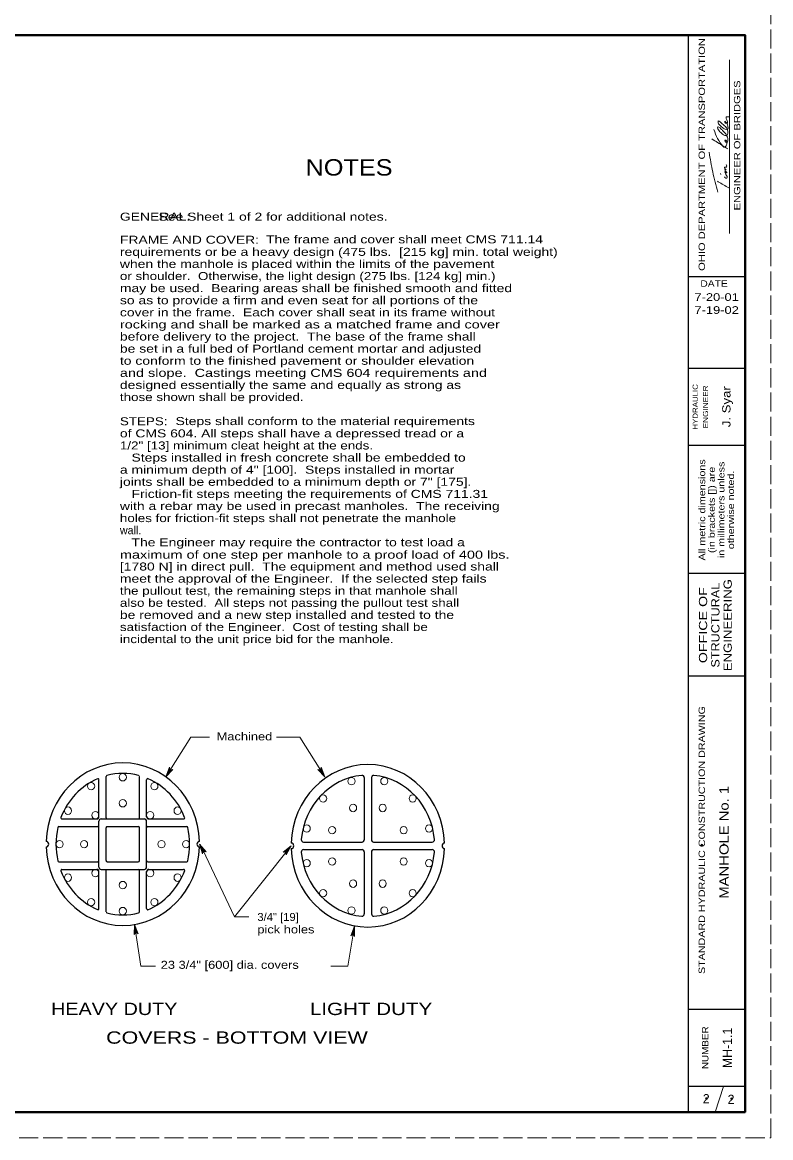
# Model space of a CAD drawing. Extents: x 1083.1 to 1117.1, y 697.4 to 741.4.
# Drawn here: x 1102.54 to 1117.13, y 697.35 to 719.1 of the extents above; entities that cross this region are included whole.
import ezdxf
from ezdxf.enums import TextEntityAlignment as Align

# ---------------------------------------------------------------- set-up
doc = ezdxf.new("R2010")
doc.units = 0
doc.header["$LTSCALE"] = 0.062
doc.header["$PDMODE"] = 32
doc.header["$PDSIZE"] = 0.031
doc.linetypes.add('LONG_DASHED', pattern=[7.5, 6, -1.5])
doc.layers.add('1', color=7, linetype='Continuous', lineweight=13)

msp = doc.modelspace()

# ---------------------------------------------------------------- linework, layer by layer
at = {"layer": '1', "lineweight": 25}
for p, q in [((1085.12642, 718.85408), (1116.62642, 718.85408)), ((1115.52642, 697.85408), (1115.52642, 718.85408)), ((1116.62642, 718.85408), (1116.62642, 697.85408)), ((1116.62642, 714.13825), (1115.52642, 714.13825)), ((1116.62642, 712.35408), (1115.52642, 712.35408)), ((1116.62642, 710.85408), (1115.52642, 710.85408)), ((1116.62642, 708.35408), (1115.52642, 708.35408)), ((1116.62642, 706.35408), (1115.52642, 706.35408)), ((1104.03592, 703.61325), (1104.03592, 704.33367)), ((1104.1765, 703.59125), (1104.1765, 704.39617)), ((1104.82367, 703.59125), (1104.82367, 704.39617)), ((1104.96425, 703.61325), (1104.96425, 704.33367)), ((1109.20633, 704.37508), (1109.20633, 703.164)), ((1109.34692, 704.37508), (1109.34692, 703.164)), ((1103.25483, 703.42042), (1104.01517, 703.42042)), ((1103.31392, 703.56925), (1103.99442, 703.56925)), ((1104.03592, 702.63042), (1104.03592, 703.52525)), ((1104.0775, 703.56925), (1104.92275, 703.56925)), ((1104.1765, 702.75725), (1104.1765, 703.39842)), ((1104.19725, 703.42042), (1104.80292, 703.42042)), ((1104.82367, 702.75725), (1104.82367, 703.39842)), ((1104.96425, 702.63042), (1104.96425, 703.52525)), ((1104.985, 703.42042), (1105.74533, 703.42042)), ((1105.00575, 703.56925), (1105.68633, 703.56925)), ((1108.02083, 703.12), (1109.16483, 703.12)), ((1108.02083, 702.97117), (1109.16483, 702.97117)), ((1109.3885, 703.12), (1110.53242, 703.12)), ((1109.3885, 702.97117), (1110.53242, 702.97117)), ((1109.20633, 702.92725), (1109.20633, 701.71608)), ((1109.34692, 702.92725), (1109.34692, 701.71608)), ((1103.25483, 702.73525), (1104.01517, 702.73525)), ((1103.31392, 702.58642), (1103.99442, 702.58642)), ((1104.03592, 701.822), (1104.03592, 702.54242)), ((1104.0775, 702.58642), (1104.92275, 702.58642)), ((1104.1765, 701.7595), (1104.1765, 702.56442)), ((1104.19725, 702.73525), (1104.80292, 702.73525)), ((1104.82367, 701.7595), (1104.82367, 702.56442)), ((1104.96425, 701.822), (1104.96425, 702.54242)), ((1104.985, 702.73525), (1105.74533, 702.73525)), ((1105.00575, 702.58642), (1105.68625, 702.58642)), ((1116.62642, 699.85408), (1115.52642, 699.85408)), ((1116.62642, 698.35408), (1115.52642, 698.35408))]:
    msp.add_line(p, q, dxfattribs=at)
at = {"layer": '1'}
for p, q in [((1116.32517, 714.98508), (1116.32517, 718.37517)), ((1116.15767, 716.136), (1116.1475, 716.15525)), ((1105.828, 705.16567), (1105.33583, 704.39183)), ((1106.19217, 705.16567), (1105.828, 705.16567)), ((1107.94875, 705.16567), (1107.49875, 705.16567)), ((1107.94875, 705.16567), (1108.44083, 704.39183)), ((1105.40967, 704.55383), (1105.33583, 704.39183)), ((1105.41675, 704.54225), (1105.33583, 704.39183)), ((1105.42625, 704.534), (1105.33583, 704.39183)), ((1105.44133, 704.52817), (1105.33583, 704.39183)), ((1105.45458, 704.52775), (1105.33583, 704.39183)), ((1108.3255, 704.52733), (1108.44083, 704.39183)), ((1108.339, 704.52892), (1108.44083, 704.39183)), ((1108.35042, 704.534), (1108.44083, 704.39183)), ((1108.36217, 704.54517), (1108.44083, 704.39183)), ((1108.36817, 704.557), (1108.44083, 704.39183)), ((1106.0775, 702.93008), (1105.99642, 703.07783)), ((1106.06508, 702.91975), (1105.99642, 703.07783)), ((1106.05833, 702.90833), (1105.99642, 703.07783)), ((1106.08925, 702.9345), (1105.99642, 703.07783)), ((1106.10283, 702.93517), (1105.99642, 703.07783)), ((1107.78033, 703.04558), (1106.67767, 701.66183)), ((1107.64375, 702.92767), (1107.78033, 703.04558)), ((1107.65683, 702.92542), (1107.78033, 703.04558)), ((1107.67092, 702.9175), (1107.78033, 703.04558)), ((1107.67917, 702.908), (1107.78033, 703.04558)), ((1107.68458, 702.89558), (1107.78033, 703.04558)), ((1104.73, 701.3335), (1104.7315, 701.51392)), ((1104.75558, 701.34717), (1104.7315, 701.51392)), ((1104.74033, 701.34183), (1104.7315, 701.51392)), ((1104.76817, 701.34717), (1104.7315, 701.51392)), ((1104.78108, 701.343), (1104.7315, 701.51392)), ((1104.7315, 701.51392), (1104.85175, 700.7015)), ((1109.01383, 701.47558), (1108.88433, 700.7015)), ((1108.956, 701.30467), (1109.01383, 701.47558)), ((1108.9685, 701.30933), (1109.01383, 701.47558)), ((1108.98458, 701.30958), (1109.01383, 701.47558)), ((1108.99658, 701.30567), (1109.01383, 701.47558)), ((1109.0075, 701.29767), (1109.01383, 701.47558)), ((1105.1375, 700.7015), (1104.85175, 700.7015)), ((1108.88433, 700.7015), (1108.55183, 700.7015)), ((1116.04308, 697.85408), (1116.20975, 698.35408))]:
    msp.add_line(p, q, dxfattribs=at)
at = {"layer": '1', "linetype": 'LONG_DASHED'}
msp.add_lwpolyline([(1083.12642, 697.35408), (1117.12642, 697.35408), (1117.12642, 719.35408), (1083.12642, 719.35408)], close=True, dxfattribs=at)
at = {"layer": '1', "lineweight": 25}
msp.add_lwpolyline([(1116.62642, 697.85408), (1085.12642, 697.85408), (1085.12642, 718.85408)], dxfattribs=at)
at = {"layer": '1', "lineweight": 40}
msp.add_lwpolyline([(1085.12642, 718.85408), (1116.62642, 718.85408), (1116.62642, 697.85408), (1085.12642, 697.85408)], close=True, dxfattribs=at)
at = {"layer": '1'}
for points in [[(1105.47317, 704.53525), (1105.33583, 704.39183), (1105.4075, 704.57708)], [(1108.36925, 704.57708), (1108.44083, 704.39183), (1108.3035, 704.53525)], [(1106.056, 702.88842), (1105.99642, 703.07783), (1106.12425, 702.92592)], [(1106.00642, 703.07533), (1106.67767, 701.66183), (1106.95633, 701.66183)], [(1107.62425, 702.92283), (1107.78033, 703.04558), (1107.6835, 702.87225)], [(1104.72075, 701.31567), (1104.7315, 701.51392), (1104.79783, 701.32683)], [(1108.94167, 701.29058), (1109.01383, 701.47558), (1109.01842, 701.277)]]:
    msp.add_lwpolyline(points, dxfattribs=at)
for centre, start, end in [((1105.44874, 704.56945), 169.63163, 305.45775), ((1108.32791, 704.5694), 234.54469, 10.37081), ((1106.09771, 702.89338), 50.8522, 186.67833), ((1107.64367, 702.88557), 341.58843, 117.41456), ((1104.7616, 701.30569), 30.29705, 166.12318), ((1108.97735, 701.26831), 12.0813, 147.90743)]:
    msp.add_arc(centre, 0.04202, start, end, dxfattribs=at)
at = {"layer": '1', "lineweight": 25}
for centre, major_axis, start_param, end_param in [((1104.50009, 703.07782), (0, -1.58419), 1.60549396, 4.67769033), ((1109.27663, 703.04562), (0, -1.58419), 1.60549396, 4.67769033), ((1104.50009, 703.07782), (0, -1.37873), 3.5296685, 4.32431274), ((1104.19729, 704.39615), (0, 0.02199), 0.23853677, 1.57079584), ((1104.50009, 703.07782), (0, -1.37873), 2.90305477, 3.38012913), ((1104.98502, 704.33368), (0, 0.02199), 5.89510863, 7.85398125), ((1104.50009, 703.07782), (0, -1.37873), 1.95887189, 2.75351705), ((1109.27663, 703.04562), (0, -1.37873), 3.23041896, 4.62356743), ((1109.16479, 704.37511), (0, 0.04397), 4.71239242, 6.37201161), ((1109.38846, 704.37511), (0, -0.04397), 3.05277314, 4.71239242), ((1109.27663, 703.04562), (0, -1.37873), 1.6596107, 3.05277314), ((1103.99439, 703.61321), (0, -0.04397), 6.28318322, 7.85397931), ((1105.00579, 703.61321), (0, 0.04397), 1.57079613, 3.14159004), ((1104.50009, 703.07782), (0, -1.37873), 4.4738511, 4.95092546), ((1103.25487, 703.3984), (0, 0.02199), 6.28318463, 7.6154439), ((1103.31388, 703.59123), (0, -0.02199), 4.32431231, 6.28318458), ((1104.01515, 703.3984), (0, 0.02199), 4.71238883, 6.28318332), ((1104.07746, 703.52526), (0, 0.04397), 6.28318317, 7.85397984), ((1104.19729, 703.59123), (0, 0.02199), 1.57079511, 3.14159261), ((1104.19729, 703.3984), (0, 0.02199), 6.28318254, 7.85397994), ((1104.80288, 703.59123), (0, -0.02199), 6.28318526, 7.85398115), ((1104.80288, 703.39839), (0, -0.02199), 1.57079511, 3.14158853), ((1104.92271, 703.52526), (0, 0.04397), 4.71238738, 6.28318448), ((1104.98502, 703.3984), (0, 0.02199), 6.2831838, 7.85397906), ((1105.6863, 703.59123), (0, -0.02199), 6.28318492, 8.24205753), ((1105.7453, 703.3984), (0, 0.02199), 4.95092575, 6.28318482), ((1104.50009, 703.07782), (0, -1.37873), 1.33225844, 1.8093328), ((1103.00375, 703.07782), (0, -0.05497), 0.01735347, 3.12425867), ((1104.50009, 703.07782), (0, -1.58419), 4.74708802, 7.81928381), ((1105.99642, 703.07782), (0, -0.05497), 3.1589244, 6.26585618), ((1107.7803, 703.04561), (0, -0.05497), 0.01735347, 3.12425867), ((1109.27663, 703.04562), (0, -1.58419), 4.74708802, 7.81928381), ((1108.02086, 703.16402), (0, -0.04397), 4.62356748, 6.28318196), ((1108.02086, 702.92721), (0, 0.04397), 6.28318177, 7.94280595), ((1109.16479, 703.16401), (0, 0.04397), 3.14158911, 4.71239237), ((1109.16479, 702.92721), (0, 0.04397), 4.71239237, 6.28318177), ((1109.38846, 703.16401), (0, -0.04397), 4.71239237, 6.28318177), ((1109.38846, 702.92721), (0, -0.04397), 3.14158911, 4.71239237), ((1110.53239, 702.9272), (0, 0.04397), 4.62355754, 6.28318196), ((1110.5324, 703.16401), (0, -0.04397), 6.28318177, 7.94279606), ((1110.77296, 703.04561), (0, -0.05497), 3.1589244, 6.26585618), ((1103.25487, 702.75725), (0, -0.02199), 4.9509258, 6.28318463), ((1104.01515, 702.75725), (0, -0.02199), 6.28318482, 7.85398154), ((1104.19729, 702.75725), (0, 0.02199), 1.57079448, 3.14159105), ((1104.80288, 702.75725), (0, -0.02199), 6.28318453, 7.85397965), ((1104.98502, 702.75725), (0, -0.02199), 4.71238641, 6.28318443), ((1105.7453, 702.75725), (0, -0.02199), 6.28318482, 7.6154439), ((1109.27663, 703.04562), (0, 1.37873), 1.65962064, 3.05277314), ((1109.27663, 703.04562), (0, 1.37873), 3.23041896, 4.62355754), ((1103.31388, 702.56442), (0, 0.02199), 6.28318458, 8.24205753), ((1104.50009, 703.07782), (0, -1.37873), 5.10046483, 5.89510965), ((1103.99439, 702.54243), (0, -0.04397), 1.5707941, 3.14159134), ((1104.07746, 702.63038), (0, 0.04397), 1.57079555, 3.14159071), ((1104.80288, 702.56442), (0, -0.02199), 1.57079575, 3.14159008), ((1104.92271, 702.63038), (0, -0.04397), 6.2831825, 7.85398018), ((1105.00579, 702.54243), (0, 0.04397), 6.28318516, 7.85398008), ((1104.50009, 703.07782), (0, -1.37873), 0.38203367, 1.18876043), ((1105.6863, 702.56442), (0, 0.02199), 4.32431231, 6.28318492), ((1104.01515, 701.82197), (0, -0.02199), 5.89510863, 7.85398091), ((1104.50009, 703.07782), (0, -1.37873), 6.04464743, 6.52172178), ((1104.80288, 701.7595), (0, -0.02199), 0.23853682, 1.57079565), ((1104.98502, 701.82197), (0, 0.02199), 1.5707956, 3.52966855), ((1109.1648, 701.71612), (0, 0.04397), 3.05277314, 4.71239237), ((1109.38847, 701.71612), (0, -0.04397), 4.71239237, 6.37201161)]:
    msp.add_ellipse(centre, major_axis=major_axis, ratio=0.944544, start_param=start_param, end_param=end_param, dxfattribs=at)
at = {"layer": '1'}
for centre, major_axis in [((1103.88356, 704.20837), (0, 0.07329)), ((1104.50008, 704.38326), (0, 0.07329)), ((1105.11661, 704.20837), (0, 0.07329)), ((1108.95749, 704.30657), (0, 0.07329)), ((1109.59576, 704.30658), (0, 0.07329)), ((1104.50008, 703.87644), (0, 0.07329)), ((1108.40473, 703.9687), (0, 0.07329)), ((1108.98796, 703.78344), (0, 0.07329)), ((1109.5653, 703.78344), (0, 0.07329)), ((1110.14852, 703.96871), (0, 0.07329)), ((1103.43224, 703.73054), (0, 0.07329)), ((1103.96669, 703.64253), (0, 0.07329)), ((1105.03348, 703.64253), (0, -0.07329)), ((1105.56793, 703.73055), (0, 0.07329)), ((1108.0856, 703.38349), (0, 0.07329)), ((1108.57972, 703.35124), (0, -0.07329)), ((1109.97354, 703.35123), (0, 0.07329)), ((1110.46766, 703.38349), (0, 0.07329)), ((1103.26704, 703.07782), (0, -0.07329)), ((1103.74576, 703.07782), (0, 0.07329)), ((1105.25442, 703.07783), (0, -0.07329)), ((1105.73313, 703.07783), (0, 0.07329)), ((1108.0856, 702.70774), (0, -0.07329)), ((1108.57972, 702.74), (0, -0.07329)), ((1109.97354, 702.74), (0, 0.07329)), ((1110.46766, 702.70775), (0, -0.07329)), ((1103.9667, 702.51312), (0, 0.07329)), ((1105.03348, 702.51312), (0, -0.07329)), ((1103.43224, 702.4251), (0, -0.07329)), ((1104.50009, 702.27921), (0, -0.07329)), ((1105.56794, 702.42511), (0, -0.07329)), ((1108.98796, 702.30779), (0, -0.07329)), ((1109.5653, 702.30779), (0, -0.07329)), ((1108.40474, 702.12253), (0, -0.07329)), ((1110.14853, 702.12254), (0, -0.07329)), ((1103.88357, 701.94728), (0, -0.07329)), ((1105.11661, 701.94728), (0, -0.07329)), ((1104.50009, 701.77239), (0, -0.07329)), ((1108.9575, 701.78466), (0, -0.07329)), ((1109.59577, 701.78466), (0, -0.07329))]:
    msp.add_ellipse(centre, major_axis=major_axis, ratio=0.944544, dxfattribs=at)
for centre, major_axis, start_param, end_param in [((1104.01515, 704.33368), (0, -0.02199), 1.57079594, 3.52966855), ((1104.80288, 704.39615), (0, -0.02199), 1.57079584, 2.90305492), ((1104.19729, 702.56442), (0, 0.02199), 6.28318279, 7.85397926), ((1104.19729, 701.7595), (0, 0.02199), 1.57079565, 2.90305492)]:
    msp.add_ellipse(centre, major_axis=major_axis, ratio=0.944544, start_param=start_param, end_param=end_param, dxfattribs=at)
for points in [[(1116.01825, 717.01108), (1116.20142, 716.68275), (1116.21658, 716.67217), (1116.22675, 716.67217), (1116.25867, 716.69583), (1116.27375, 716.73), (1116.26875, 716.78125), (1116.25183, 716.80308), (1116.23833, 716.80308), (1116.23658, 716.79008), (1116.24675, 716.77492), (1116.26025, 716.7665), (1116.27533, 716.7665), (1116.2905, 716.78808), (1116.29392, 716.80742), (1116.28367, 716.86275), (1116.20142, 716.98317), (1116.15592, 717.02783), (1116.119, 717.06242), (1116.09383, 717.06458), (1116.09558, 717.026), (1116.12075, 716.98725), (1116.188, 716.92492), (1116.23008, 716.8995), (1116.26375, 716.895), (1116.28708, 716.921), (1116.29392, 716.95517), (1116.28883, 716.98092), (1116.25867, 717.05408), (1116.22842, 717.08608), (1116.16783, 717.1395), (1116.13917, 717.16533), (1116.10567, 717.18058), (1116.10225, 717.15258), (1116.11233, 717.12675), (1116.1695, 717.06683), (1116.24017, 717.01958), (1116.29217, 717.02192), (1116.2905, 717.07958), (1116.27867, 717.1225), (1116.26533, 717.14825), (1116.25517, 717.159), (1116.23175, 717.174), (1116.2335, 717.15692), (1116.26875, 717.13542), (1116.28367, 717.14617), (1116.27058, 717.19983), (1116.262, 717.22775), (1116.25867, 717.24042), (1116.25867, 717.25325), (1116.25867, 717.26192), (1116.28367, 717.25975), (1116.30908, 717.25975)], [(1115.97942, 716.82883), (1116.20317, 716.69133), (1116.28883, 716.63567)], [(1116.09567, 715.79183), (1115.997, 716.18708), (1115.92575, 716.56942)], [(1116.22675, 716.09075), (1116.235, 716.08008), (1116.27217, 716.06717), (1116.27692, 716.09958), (1116.25183, 716.136), (1116.23658, 716.17225), (1116.23658, 716.1915), (1116.25183, 716.18525), (1116.262, 716.17442), (1116.27217, 716.17008), (1116.2485, 716.20225), (1116.23658, 716.21725), (1116.2335, 716.23458), (1116.25692, 716.228), (1116.2485, 716.23667), (1116.22333, 716.2645), (1116.2335, 716.27967), (1116.25025, 716.28167), (1116.25867, 716.27967), (1116.26875, 716.301), (1116.262, 716.32892)], [(1116.31083, 715.87625), (1116.10567, 715.99625), (1116.09008, 716.00667)]]:
    msp.add_spline(points, degree=3, dxfattribs=at)
for p in [(1115.78383, 703.06008), (1116.21667, 703.06742), (1115.8745, 698.11783), (1116.36292, 698.11683)]:
    msp.add_point(p, dxfattribs=at)

# ---------------------------------------------------------------- texts
for s, height, width, p in [('OHIO DEPARTMENT OF TRANSPORTATION', 0.125, 1.3, (1115.84633, 716.52633)), ('ENGINEER OF BRIDGES', 0.125, 1.3, (1116.53467, 716.70312)), ('HYDRAULIC', 0.1, 1.15, (1115.7055, 711.60517)), ('ENGINEER', 0.1, 1.2, (1115.90642, 711.60521)), ('J. Syar', 0.16, 1.2, (1116.34283, 711.60821)), ('All metric dimensions', 0.125, 1.25, (1115.85025, 709.59617)), ('(in brackets []) are', 0.125, 1.25, (1116.03775, 709.59617)), ('in millimeters unless', 0.125, 1.25, (1116.22525, 709.59621)), ('otherwise noted.', 0.125, 1.25, (1116.41275, 709.59617)), ('ENGINEERING', 0.16, 1.2, (1116.36817, 707.34862)), ('OFFICE OF', 0.16, 1.3, (1115.88817, 707.34854)), ('STRUCTURAL', 0.16, 1.15, (1116.12817, 707.34854)), ('STANDARD HYDRAULIC CONSTRUCTION DRAWING', 0.125, 1.25, (1115.84633, 703.15812)), ('MANHOLE No. 1', 0.18, 1.2, (1116.30683, 703.11421)), ('NUMBER', 0.125, 1.15, (1115.91342, 699.10817))]:
    msp.add_text(s, height=height, rotation=90, dxfattribs=dict(at, width=width)).set_placement(p, align=Align.CENTER)
for s, height, width, p in [('NOTES', 0.32, 1.15, (1108.06242, 716.11525)), ('GENERAL: ', 0.156, 1.3, (1104.44383, 715.23617)), ('          See Sheet 1 of 2 for additional notes.', 0.156, 1.3, (1104.44383, 715.23617)), ('FRAME AND COVER: ', 0.156, 1.3, (1104.44383, 714.78617)), ('The frame and cover shall meet CMS 711.14', 0.156, 1.3, (1107.29158, 714.79367)), ('requirements or be a heavy design (475 lbs.  [215 kg] min. total weight)', 0.156, 1.3, (1104.44383, 714.55017)), ('when the manhole is placed within the limits of the pavement', 0.156, 1.3, (1104.44383, 714.31417)), ('or shoulder.  Otherwise, the light design (275 lbs. [124 kg] min.)', 0.156, 1.25, (1104.44383, 714.07817)), ('may be used.  Bearing areas shall be finished smooth and fitted', 0.156, 1.3, (1104.44383, 713.84217)), ('so as to provide a firm and even seat for all portions of the', 0.156, 1.3, (1104.44383, 713.60617)), ('cover in the frame.  Each cover shall seat in its frame without', 0.156, 1.3, (1104.44383, 713.37017)), ('rocking and shall be marked as a matched frame and cover', 0.156, 1.35, (1104.44383, 713.13417)), ('before delivery to the project.  The base of the frame shall', 0.156, 1.3, (1104.44383, 712.89817)), ('be set in a full bed of Portland cement mortar and adjusted', 0.156, 1.3, (1104.44383, 712.66217)), ('to conform to the finished pavement or shoulder elevation', 0.156, 1.3, (1104.44383, 712.42617)), ('and slope.  Castings meeting CMS 604 requirements and', 0.156, 1.35, (1104.44383, 712.19017)), ('designed essentially the same and equally as strong as', 0.156, 1.3, (1104.44383, 711.95417)), ('those shown shall be provided.', 0.156, 1.25, (1104.44383, 711.71817)), ('STEPS:', 0.156, 1.25, (1104.44383, 711.24617)), ('Steps shall conform to the material requirements', 0.156, 1.3, (1105.52883, 711.24992)), ('of CMS 604. All steps shall have a depressed tread or a', 0.156, 1.3, (1104.44383, 711.01017)), ('1/2" [13] minimum cleat height at the ends.', 0.156, 1.25, (1104.44383, 710.77417)), ('   Steps installed in fresh concrete shall be embedded to', 0.156, 1.3, (1104.44383, 710.53817)), ('a minimum depth of 4" [100].  Steps installed in mortar', 0.156, 1.3, (1104.44383, 710.30217)), ('joints shall be embedded to a minimum depth or 7" [175].', 0.156, 1.3, (1104.44383, 710.06617)), ('   Friction-fit steps meeting the requirements of CMS 711.31', 0.156, 1.3, (1104.44383, 709.83017)), ('with a rebar may be used in precast manholes.  The receiving', 0.156, 1.3, (1104.44383, 709.59417)), ('holes for friction-fit steps shall not penetrate the manhole', 0.156, 1.25, (1104.44383, 709.35817)), ('   The Engineer may require the contractor to test load a', 0.156, 1.3, (1104.44383, 708.88617)), ('maximum of one step per manhole to a proof load of 400 lbs.', 0.156, 1.35, (1104.44383, 708.64508)), ('[1780 N] in direct pull.  The equipment and method used shall', 0.156, 1.3, (1104.44383, 708.41417)), ('meet the approval of the Engineer.  If the selected step fails', 0.156, 1.3, (1104.44383, 708.17817)), ('the pullout test, the remaining steps in that manhole shall', 0.156, 1.25, (1104.44383, 707.94217)), ('also be tested.  All steps not passing the pullout test shall', 0.156, 1.25, (1104.44383, 707.70617)), ('be removed and a new step installed and tested to the', 0.156, 1.3, (1104.44383, 707.47017)), ('satisfaction of the Engineer.  Cost of testing shall be', 0.156, 1.25, (1104.44383, 707.23417)), ('incidental to the unit price bid for the manhole.', 0.156, 1.25, (1104.44383, 706.99817)), ('Machined', 0.156, 1.2, (1106.32842, 705.1015)), ('3/4" [19]', 0.156, 1.05, (1107.12233, 701.58)), ('pick holes', 0.156, 1.2, (1107.12233, 701.3375)), ('23 3/4" [600] dia. covers', 0.156, 1.2, (1105.23883, 700.64717)), ('HEAVY DUTY', 0.24, 1.2, (1103.10292, 699.74558)), ('LIGHT DUTY', 0.24, 1.25, (1108.1465, 699.74558)), ('COVERS - BOTTOM VIEW', 0.24, 1.3, (1104.17508, 699.18708))]:
    msp.add_text(s, height=height, dxfattribs=dict(at, width=width)).set_placement(p)
for s, height, width, p in [('DATE', 0.125, 1.2, (1116.02312, 713.94683)), ('7-20-01', 0.15, 1.25, (1116.07346, 713.67133)), ('7-19-02', 0.15, 1.25, (1116.07346, 713.41825))]:
    msp.add_text(s, height=height, dxfattribs=dict(at, width=width)).set_placement(p, align=Align.CENTER)
msp.add_text('wall.', height=0.156, dxfattribs=at).set_placement((1104.44383, 709.12217))
msp.add_text('MH-1.1', height=0.18, rotation=90, dxfattribs=at).set_placement((1116.3725, 699.10442), align=Align.CENTER)
for p in [(1115.87088, 698.02417), (1116.35371, 698.01158)]:
    msp.add_text('2', height=0.18, dxfattribs=at).set_placement(p, align=Align.CENTER)

doc.saveas('drawing.dxf')
